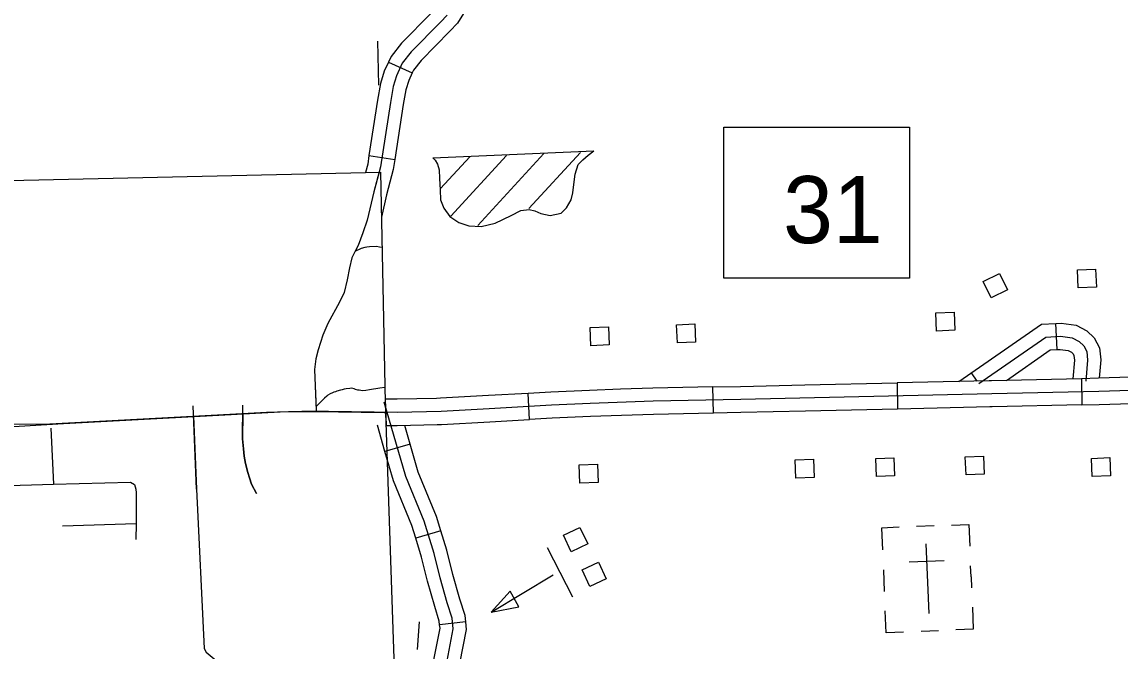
# Model space of a CAD drawing. Extents: x 1671357 to 13005564, y 567358 to 14261451.
# Drawn here: x 12758299.486 to 12758301.586, y 14259946.261 to 14259947.463 of the extents above; entities that cross this region are included whole.
import ezdxf

# ---------------------------------------------------------------- set-up
doc = ezdxf.new("R2010")
doc.units = 0
for name, color, linetype in [('31', 7, 'Continuous'), ('32', 7, 'Continuous'), ('33', 7, 'Continuous'), ('34', 7, 'Continuous'), ('5', 7, 'Continuous'), ('56', 7, 'Continuous'), ('6', 7, 'Continuous'), ('Default', 7, 'Continuous')]:
    doc.layers.add(name, color=color, linetype=linetype)

msp = doc.modelspace()

# ---------------------------------------------------------------- linework, layer by layer
at = {"layer": '31'}
for p, q in [((12758301.5123, 14259946.7813), (12758301.5134, 14259946.7312)), ((12758300.457, 14259946.7033), (12758300.4542, 14259946.7533)), ((12758300.4542, 14259946.7533), (12758300.4542, 14259946.7533)), ((12758300.8084, 14259946.7154), (12758300.8074, 14259946.7655)), ((12758301.1598, 14259946.7733), (12758301.1609, 14259946.7232)), ((12758300.279, 14259946.7436), (12758300.279, 14259946.7436))]:
    msp.add_line(p, q, dxfattribs=at)
for points in [[(12758302.4548, 14259946.7854), (12758301.5458, 14259946.757), (12758301.3412, 14259946.7523), (12758300.8608, 14259946.7415), (12758300.6934, 14259946.7381), (12758300.5726, 14259946.7339), (12758300.4989, 14259946.7308), (12758300.3795, 14259946.724), (12758300.2875, 14259946.7187), (12758300.2035, 14259946.7169), (12758300.0723, 14259946.7183), (12758300.0211, 14259946.7184), (12758299.9797, 14259946.717), (12758299.839, 14259946.7097), (12758299.5656, 14259946.695), (12758299.3954, 14259946.685)], [(12758301.336, 14259946.7773), (12758301.1598, 14259946.7733)], [(12758301.5123, 14259946.7813), (12758301.3406, 14259946.7774), (12758301.336, 14259946.7773)], [(12758301.6883, 14259946.7865), (12758301.5452, 14259946.7821), (12758301.5123, 14259946.7813)], [(12758300.4542, 14259946.7533), (12758300.3781, 14259946.749), (12758300.2865, 14259946.7438), (12758300.279, 14259946.7436)], [(12758300.6308, 14259946.761), (12758300.5717, 14259946.759), (12758300.4977, 14259946.7558), (12758300.4542, 14259946.7533)], [(12758300.8074, 14259946.7655), (12758300.6927, 14259946.7631), (12758300.6308, 14259946.761)], [(12758300.8074, 14259946.7655), (12758300.8602, 14259946.7666), (12758300.9836, 14259946.7693)], [(12758300.9836, 14259946.7693), (12758301.1598, 14259946.7733)], [(12758300.279, 14259946.7436), (12758300.2034, 14259946.7419), (12758300.1808, 14259946.7421)], [(12758300.1808, 14259946.7421), (12758300.1824, 14259946.692), (12758300.2037, 14259946.6918), (12758300.2801, 14259946.6935)], [(12758301.5134, 14259946.7312), (12758301.5465, 14259946.732), (12758301.6898, 14259946.7365)], [(12758300.6325, 14259946.7109), (12758300.5736, 14259946.7089), (12758300.5002, 14259946.7058), (12758300.457, 14259946.7033)], [(12758300.8084, 14259946.7154), (12758300.6941, 14259946.7131), (12758300.6325, 14259946.7109)], [(12758300.9847, 14259946.7193), (12758300.8613, 14259946.7165), (12758300.8084, 14259946.7154)], [(12758301.1609, 14259946.7232), (12758300.9847, 14259946.7193)], [(12758301.3372, 14259946.7272), (12758301.1609, 14259946.7232)], [(12758301.5134, 14259946.7312), (12758301.3418, 14259946.7273), (12758301.3372, 14259946.7272)], [(12758300.2801, 14259946.6935), (12758300.2885, 14259946.6937), (12758300.3809, 14259946.699), (12758300.457, 14259946.7033)]]:
    msp.add_lwpolyline(points, dxfattribs=at)
at = {"layer": '32'}
for p, q in [((12758300.187, 14259947.3868), (12758300.2325, 14259947.3659)), ((12758300.1497, 14259947.2081), (12758300.1993, 14259947.2005)), ((12758301.466, 14259946.837), (12758301.4633, 14259946.887)), ((12758301.3129, 14259946.7767), (12758301.3019, 14259946.7925)), ((12758300.2284, 14259946.6563), (12758300.1803, 14259946.6423)), ((12758300.2872, 14259946.4907), (12758300.2393, 14259946.4761)), ((12758300.3347, 14259946.3163), (12758300.2849, 14259946.3108))]:
    msp.add_line(p, q, dxfattribs=at)
for points in [[(12758300.2938, 14259947.5228), (12758300.2857, 14259947.502), (12758300.2794, 14259947.4919), (12758300.2686, 14259947.4804), (12758300.2117, 14259947.4229), (12758300.1919, 14259947.3976), (12758300.187, 14259947.3868)], [(12758300.3404, 14259947.5044), (12758300.3306, 14259947.4794), (12758300.3193, 14259947.4613), (12758300.3046, 14259947.4456), (12758300.2494, 14259947.3897), (12758300.235, 14259947.3713), (12758300.2325, 14259947.3659)], [(12758300.2994, 14259947.4766), (12758300.2866, 14259947.463), (12758300.2306, 14259947.4063), (12758300.2135, 14259947.3845), (12758300.2025, 14259947.3605), (12758300.196, 14259947.3398), (12758300.1906, 14259947.3097), (12758300.1718, 14259947.1866), (12758300.1588, 14259947.1388), (12758300.1464, 14259947.0843), (12758300.1378, 14259947.0602), (12758300.1291, 14259947.0363), (12758300.1236, 14259947.0254), (12758300.1171, 14259947.0127), (12758300.1126, 14259946.9931), (12758300.1082, 14259946.9701), (12758300.1022, 14259946.9464), (12758300.0933, 14259946.9279), (12758300.071, 14259946.8867), (12758300.0613, 14259946.8648), (12758300.0525, 14259946.8363), (12758300.0482, 14259946.8194), (12758300.0454, 14259946.7991), (12758300.048, 14259946.7379)], [(12758300.187, 14259947.3868), (12758300.179, 14259947.3695), (12758300.1716, 14259947.3458), (12758300.1659, 14259947.3139), (12758300.1497, 14259947.2081)], [(12758300.2325, 14259947.3659), (12758300.2259, 14259947.3515), (12758300.2204, 14259947.3338), (12758300.2153, 14259947.3056), (12758300.1993, 14259947.2005)], [(12758300.1497, 14259947.2081), (12758300.1473, 14259947.1918), (12758300.1428, 14259947.1756)], [(12758300.1993, 14259947.2005), (12758300.1963, 14259947.1814), (12758300.1831, 14259947.1327), (12758300.1734, 14259947.0899)], [(12758301.2781, 14259946.776), (12758301.4359, 14259946.8855), (12758301.4633, 14259946.887)], [(12758301.4633, 14259946.887), (12758301.4735, 14259946.8875), (12758301.5021, 14259946.8839), (12758301.5229, 14259946.8731), (12758301.5371, 14259946.8594), (12758301.5471, 14259946.8404), (12758301.5495, 14259946.8172), (12758301.5463, 14259946.7821)], [(12758301.3162, 14259946.7719), (12758301.4443, 14259946.8609), (12758301.4726, 14259946.8624), (12758301.4945, 14259946.8596), (12758301.5081, 14259946.8525), (12758301.5168, 14259946.8442), (12758301.5227, 14259946.833), (12758301.5243, 14259946.817), (12758301.5207, 14259946.7766)], [(12758301.3689, 14259946.778), (12758301.4528, 14259946.8362), (12758301.466, 14259946.837)], [(12758301.466, 14259946.837), (12758301.4718, 14259946.8373), (12758301.4869, 14259946.8354), (12758301.4934, 14259946.832), (12758301.4965, 14259946.8289), (12758301.4982, 14259946.8257), (12758301.4992, 14259946.8168), (12758301.496, 14259946.7809)], [(12758300.2062, 14259946.0174), (12758300.2528, 14259946.014), (12758300.256, 14259946.0564), (12758300.2642, 14259946.0993), (12758300.2787, 14259946.1512), (12758300.2992, 14259946.2419), (12758300.311, 14259946.3031), (12758300.3088, 14259946.3231), (12758300.2995, 14259946.3525), (12758300.2861, 14259946.4005), (12758300.2744, 14259946.447), (12758300.2554, 14259946.5092), (12758300.2204, 14259946.5941), (12758300.1789, 14259946.7365)], [(12758299.82, 14259946.57), (12758299.8132, 14259946.7292)], [(12758299.9345, 14259946.5616), (12758299.9252, 14259946.5794), (12758299.9214, 14259946.5917), (12758299.918, 14259946.602), (12758299.9135, 14259946.6189), (12758299.9113, 14259946.6332), (12758299.9098, 14259946.6469), (12758299.9078, 14259946.6663), (12758299.9085, 14259946.731)], [(12758300.1803, 14259946.6423), (12758300.1658, 14259946.6922)], [(12758300.2284, 14259946.6563), (12758300.2181, 14259946.6917)], [(12758300.2872, 14259946.4907), (12758300.279, 14259946.5176), (12758300.2441, 14259946.6024), (12758300.2284, 14259946.6563)], [(12758300.2393, 14259946.4761), (12758300.2318, 14259946.5007), (12758300.1967, 14259946.5858), (12758300.1803, 14259946.6423)], [(12758300.3347, 14259946.3163), (12758300.3334, 14259946.3282), (12758300.3235, 14259946.3596), (12758300.3103, 14259946.4069), (12758300.2986, 14259946.4537), (12758300.2872, 14259946.4907)], [(12758300.2849, 14259946.3108), (12758300.2841, 14259946.3179), (12758300.2755, 14259946.3454), (12758300.2619, 14259946.3941), (12758300.2503, 14259946.4402), (12758300.2393, 14259946.4761)], [(12758300.3, 14259946.1344), (12758300.303, 14259946.1451), (12758300.3237, 14259946.2368), (12758300.3363, 14259946.302), (12758300.3347, 14259946.3163)], [(12758300.2517, 14259946.1478), (12758300.2544, 14259946.1573), (12758300.2747, 14259946.247), (12758300.2856, 14259946.3041), (12758300.2849, 14259946.3108)]]:
    msp.add_lwpolyline(points, dxfattribs=at)
at = {"layer": '33'}
for points in [[(12758299.3996, 14259946.6941), (12758299.5392, 14259946.6949), (12758299.8128, 14259946.7096), (12758299.9537, 14259946.717), (12758299.9957, 14259946.7184), (12758300.0475, 14259946.7183), (12758300.1785, 14259946.7168), (12758300.1804, 14259946.7169)], [(12758299.541, 14259946.6869), (12758299.5461, 14259946.5798)], [(12758299.3547, 14259946.5736), (12758299.5461, 14259946.5798), (12758299.6935, 14259946.5837), (12758299.7011, 14259946.579), (12758299.7038, 14259946.5701), (12758299.7041, 14259946.563), (12758299.7046, 14259946.5037), (12758299.7036, 14259946.4739)], [(12758299.7046, 14259946.5037), (12758299.5636, 14259946.4991)]]:
    msp.add_lwpolyline(points, dxfattribs=at)
at = {"layer": '34'}
for points in [[(12758300.169, 14259947.1761), (12758300.1588, 14259947.1388), (12758300.1464, 14259947.0843), (12758300.1378, 14259947.0602), (12758300.1291, 14259947.0363), (12758300.1236, 14259947.0254), (12758300.1171, 14259947.0127), (12758300.1126, 14259946.9931), (12758300.1082, 14259946.9701), (12758300.1022, 14259946.9464), (12758300.0933, 14259946.9279), (12758300.071, 14259946.8867), (12758300.0613, 14259946.8648), (12758300.0525, 14259946.8363), (12758300.0482, 14259946.8194), (12758300.0454, 14259946.7991), (12758300.0487, 14259946.7203)], [(12758300.1234, 14259947.0249), (12758300.1356, 14259947.0306), (12758300.1422, 14259947.0325), (12758300.1458, 14259947.0334), (12758300.1508, 14259947.0343), (12758300.1641, 14259947.0345), (12758300.1699, 14259947.0334), (12758300.1746, 14259947.0331)], [(12758300.1708, 14259946.7632), (12758300.1505, 14259946.76), (12758300.1435, 14259946.7587), (12758300.1372, 14259946.7584), (12758300.1308, 14259946.7591), (12758300.1285, 14259946.7594), (12758300.1241, 14259946.7609), (12758300.1214, 14259946.7618), (12758300.117, 14259946.7629), (12758300.113, 14259946.7627), (12758300.106, 14259946.7621), (12758300.1024, 14259946.7613), (12758300.0984, 14259946.7601), (12758300.0954, 14259946.7593), (12758300.0885, 14259946.7573), (12758300.0859, 14259946.7565), (12758300.0826, 14259946.7554), (12758300.0799, 14259946.7543), (12758300.0753, 14259946.7524), (12758300.0711, 14259946.7499), (12758300.0689, 14259946.7478), (12758300.0644, 14259946.7439), (12758300.0495, 14259946.7288)], [(12758300.1803, 14259946.7645), (12758300.1708, 14259946.7632)], [(12758299.9084, 14259946.7146), (12758299.9078, 14259946.6663), (12758299.9098, 14259946.6469), (12758299.9113, 14259946.6332), (12758299.9135, 14259946.6189), (12758299.918, 14259946.602), (12758299.9214, 14259946.5917), (12758299.9252, 14259946.5794), (12758299.9345, 14259946.5616)], [(12758299.8141, 14259946.7097), (12758299.82, 14259946.57)], [(12758299.82, 14259946.57), (12758299.8347, 14259946.2653), (12758299.8386, 14259946.2584), (12758299.8574, 14259946.2425), (12758299.8666, 14259946.2305), (12758299.8777, 14259946.1971), (12758299.9022, 14259946.1619), (12758299.9459, 14259946.1541), (12758299.974, 14259946.1546), (12758300.0182, 14259946.1595), (12758300.0413, 14259946.1662), (12758300.0694, 14259946.1801), (12758300.0916, 14259946.1831), (12758300.1165, 14259946.1788), (12758300.2008, 14259946.1481)]]:
    msp.add_lwpolyline(points, dxfattribs=at)
at = {"layer": '5'}
msp.add_lwpolyline([(12758300.1662, 14259947.4268), (12758300.168, 14259947.3424)], dxfattribs=at)
at = {"layer": '56'}
for p, q in [((12758300.2716, 14259947.2037), (12758300.5798, 14259947.2168)), ((12758300.2868, 14259947.145), (12758300.3424, 14259947.2055)), ((12758300.3063, 14259947.0922), (12758300.4127, 14259947.2081)), ((12758300.3579, 14259947.0744), (12758300.484, 14259947.2117)), ((12758300.4554, 14259947.1065), (12758300.5542, 14259947.2141)), ((12758301.2305, 14259946.4999), (12758301.1971, 14259946.4985)), ((12758301.2151, 14259946.4658), (12758301.2208, 14259946.3324)), ((12758301.1831, 14259946.4311), (12758301.2501, 14259946.4339)), ((12758301.3013, 14259946.4027), (12758301.3004, 14259946.4232)), ((12758300.3834, 14259946.3349), (12758300.502, 14259946.4062)), ((12758301.1336, 14259946.4161), (12758301.1354, 14259946.3744)), ((12758301.2179, 14259946.3991), (12758301.2179, 14259946.3991)), ((12758301.2179, 14259946.3991), (12758301.2179, 14259946.3991)), ((12758301.3013, 14259946.4027), (12758301.3022, 14259946.3815)), ((12758301.2057, 14259946.2983), (12758301.239, 14259946.2998))]:
    msp.add_line(p, q, dxfattribs=at)
for points in [[(12758300.2716, 14259947.2037), (12758300.2762, 14259947.199), (12758300.2806, 14259947.1918), (12758300.2839, 14259947.1809), (12758300.2846, 14259947.1643), (12758300.286, 14259947.1427), (12758300.2868, 14259947.1233), (12758300.293, 14259947.1075), (12758300.3043, 14259947.0913), (12758300.3214, 14259947.0801), (12758300.341, 14259947.0735), (12758300.3646, 14259947.0722), (12758300.3911, 14259947.0784), (12758300.4214, 14259947.0936), (12758300.4399, 14259947.1027), (12758300.456, 14259947.1047), (12758300.4671, 14259947.102), (12758300.4784, 14259947.0969), (12758300.4966, 14259947.0935), (12758300.5171, 14259947.0981), (12758300.5278, 14259947.1078), (12758300.5364, 14259947.1234), (12758300.5399, 14259947.1369), (12758300.5416, 14259947.1527), (12758300.5444, 14259947.1726), (12758300.5501, 14259947.1909), (12758300.5585, 14259947.1995), (12758300.5692, 14259947.2087), (12758300.5798, 14259947.2168)], [(12758301.2637, 14259946.5013), (12758301.297, 14259946.5027), (12758301.2988, 14259946.4611)], [(12758301.1636, 14259946.4971), (12758301.1302, 14259946.4956), (12758301.132, 14259946.4539)], [(12758300.4907, 14259946.4585), (12758300.5393, 14259946.3644)], [(12758301.1721, 14259946.2969), (12758301.1388, 14259946.2955), (12758301.137, 14259946.3372)], [(12758301.3038, 14259946.3443), (12758301.3056, 14259946.3026), (12758301.2722, 14259946.3012)], [(12758300.2455, 14259946.3161), (12758300.2421, 14259946.2633)]]:
    msp.add_lwpolyline(points, dxfattribs=at)
for points in [[(12758301.5063, 14259946.9548), (12758301.5048, 14259946.9895), (12758301.5397, 14259946.991), (12758301.5411, 14259946.9563)], [(12758301.3398, 14259946.9359), (12758301.3245, 14259946.9671), (12758301.3558, 14259946.9825), (12758301.3711, 14259946.9513)], [(12758301.2355, 14259946.8724), (12758301.234, 14259946.9071), (12758301.2688, 14259946.9086), (12758301.2703, 14259946.8739)], [(12758300.5743, 14259946.8444), (12758300.5728, 14259946.8791), (12758300.6077, 14259946.8806), (12758300.6091, 14259946.8459)], [(12758300.7397, 14259946.8497), (12758300.7382, 14259946.8844), (12758300.773, 14259946.8859), (12758300.7745, 14259946.8512)], [(12758300.9664, 14259946.5912), (12758300.9649, 14259946.6259), (12758300.9998, 14259946.6274), (12758301.0012, 14259946.5927)], [(12758301.1204, 14259946.594), (12758301.1189, 14259946.6287), (12758301.1538, 14259946.6302), (12758301.1552, 14259946.5955)], [(12758301.2918, 14259946.5972), (12758301.2903, 14259946.632), (12758301.3252, 14259946.6334), (12758301.3266, 14259946.5987)], [(12758301.5333, 14259946.5942), (12758301.5319, 14259946.6289), (12758301.5667, 14259946.6304), (12758301.5682, 14259946.5956)], [(12758300.5533, 14259946.5817), (12758300.5518, 14259946.6164), (12758300.5866, 14259946.6179), (12758300.5881, 14259946.5831)], [(12758300.5366, 14259946.4504), (12758300.5218, 14259946.4819), (12758300.5533, 14259946.4967), (12758300.5681, 14259946.4653)], [(12758300.572, 14259946.3841), (12758300.5574, 14259946.4156), (12758300.589, 14259946.4302), (12758300.6036, 14259946.3987)], [(12758300.4363, 14259946.3452), (12758300.4196, 14259946.3748), (12758300.3834, 14259946.3349)]]:
    msp.add_lwpolyline(points, close=True, dxfattribs=at)
at = {"layer": '6'}
for points in [[(12758299.2901, 14259947.1566), (12758300.1715, 14259947.1762)], [(12758300.1715, 14259947.1762), (12758300.1775, 14259946.8953), (12758300.1809, 14259946.7352), (12758300.1963, 14259946.2831), (12758300.2111, 14259945.8444)]]:
    msp.add_lwpolyline(points, dxfattribs=at)
at = {"layer": 'Default'}
msp.add_lwpolyline([(12758300.8287, 14259947.2623), (12758301.1833, 14259947.2623), (12758301.1833, 14259946.9733), (12758300.8287, 14259946.9733)], close=True, dxfattribs=at)

# ---------------------------------------------------------------- texts
msp.add_text('31', height=0.12825, dxfattribs=at).set_placement((12758300.9418, 14259947.0405))

doc.saveas('drawing.dxf')
